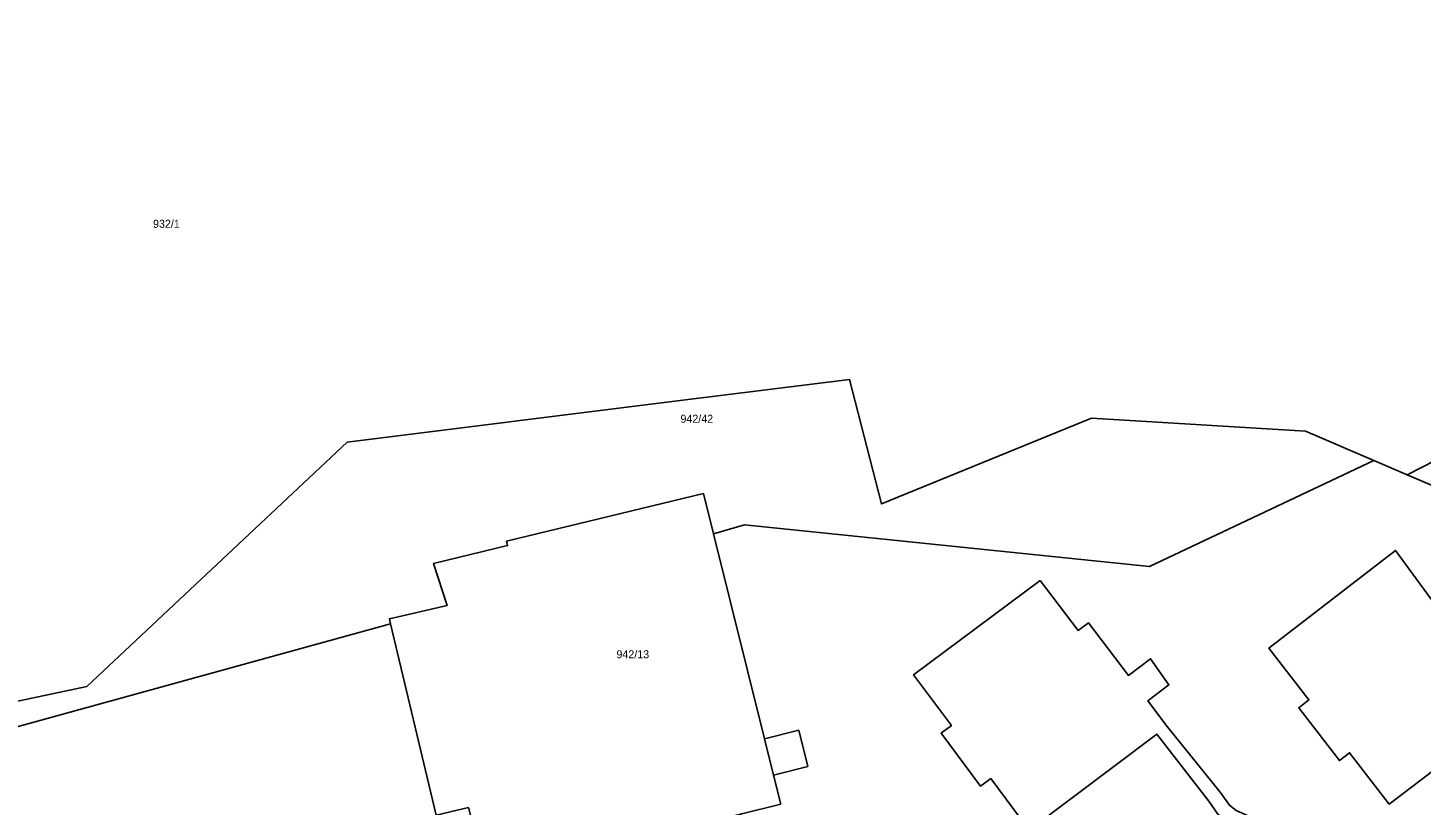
# Model space of a CAD drawing. Extents: x -793400 to -756198, y -1074141 to -1042963.
# Drawn here: x -783099 to -782968.4, y -1065113.7 to -1065040.9 of the extents above; entities that cross this region are included whole.
import ezdxf

# ---------------------------------------------------------------- set-up
doc = ezdxf.new("R2010")
doc.units = 0
for name, color, linetype in [('Parcela', 7, 'Continuous'), ('Popiskový text - Parcela', 7, 'Continuous'), ('Stavební objekt', 7, 'Continuous')]:
    doc.layers.add(name, color=color, linetype=linetype)

msp = doc.modelspace()

# ---------------------------------------------------------------- linework, layer by layer
at = {"layer": 'Parcela'}
for points in [[(-782898.51, -1065020.62), (-782948.33, -1065054.83), (-782960.53, -1065078.04), (-782969.74, -1065082.74), (-782972.88, -1065081.39), (-782979.27, -1065078.65), (-782999.34, -1065077.44), (-783019.03, -1065085.47), (-783022.01, -1065073.82), (-783037.89, -1065075.79), (-783069.1, -1065079.67), (-783093.52, -1065102.56), (-783130.63, -1065110.44), (-783148.72, -1065112.77), (-783166.26, -1065118.6), (-783200, -1065130.88), (-783236.01, -1065137.59), (-783242.83, -1065136.63), (-783249.82, -1065138.12)], [(-783130.63, -1065110.44), (-783093.52, -1065102.56), (-783069.1, -1065079.67), (-783037.89, -1065075.79), (-783022.01, -1065073.82), (-783019.03, -1065085.47), (-782999.34, -1065077.44), (-782979.27, -1065078.65), (-782972.88, -1065081.39), (-782993.91, -1065091.32), (-783031.87, -1065087.44), (-783034.78, -1065088.26), (-783035.72, -1065084.5), (-783054.18, -1065088.96), (-783054.08, -1065089.37), (-783061.01, -1065091.04), (-783059.74, -1065094.99), (-783065.15, -1065096.23), (-783065.04, -1065096.7), (-783145.19, -1065118.78)], [(-783145.19, -1065118.78), (-783065.04, -1065096.7), (-783060.76, -1065114.64), (-783057.74, -1065113.92), (-783056.04, -1065120.47), (-783037.14, -1065115.76), (-783036.87, -1065116.85), (-783031.97, -1065115.65), (-783032.24, -1065114.53), (-783028.46, -1065113.59), (-783029.14, -1065110.87), (-783025.94, -1065110.07), (-783026.78, -1065106.68), (-783029.99, -1065107.48), (-783034.78, -1065088.26), (-783031.87, -1065087.44), (-782993.91, -1065091.32), (-782972.88, -1065081.39), (-782969.74, -1065082.74), (-782964.46, -1065085)], [(-782967.25, -1065094.75), (-782970.84, -1065089.82), (-782982.71, -1065098.98), (-782978.96, -1065103.83), (-782979.91, -1065104.56), (-782976.09, -1065109.51), (-782975.14, -1065108.78), (-782971.43, -1065113.59), (-782959.66, -1065104.63)]]:
    msp.add_lwpolyline(points, dxfattribs=at)
for points in [[(-783034.78, -1065088.26), (-783029.99, -1065107.48), (-783026.78, -1065106.68), (-783025.94, -1065110.07), (-783029.14, -1065110.87), (-783028.46, -1065113.59), (-783032.24, -1065114.53), (-783031.97, -1065115.65), (-783036.87, -1065116.85), (-783037.14, -1065115.76), (-783056.04, -1065120.47), (-783057.74, -1065113.92), (-783060.76, -1065114.64), (-783065.04, -1065096.7), (-783065.15, -1065096.23), (-783059.74, -1065094.99), (-783061.01, -1065091.04), (-783054.08, -1065089.37), (-783054.18, -1065088.96), (-783035.72, -1065084.5)], [(-783004.14, -1065092.63), (-783016.02, -1065101.47), (-783012.47, -1065106.24), (-783013.43, -1065106.95), (-783009.74, -1065111.92), (-783008.78, -1065111.2), (-783005.18, -1065116.04), (-782993.21, -1065107.04), (-782988.33, -1065113.31), (-782987.48, -1065114.54), (-782986.34, -1065115.46), (-782979.93, -1065118.16), (-782981.55, -1065116.06), (-782985.78, -1065114.21), (-782986.41, -1065113.7), (-782987.26, -1065112.48), (-782992.25, -1065106.31), (-782994.06, -1065103.93), (-782992.08, -1065102.43), (-782993.8, -1065099.97), (-782995.87, -1065101.54), (-782999.62, -1065096.6), (-783000.58, -1065097.33)]]:
    msp.add_lwpolyline(points, close=True, dxfattribs=at)
at = {"layer": 'Stavební objekt'}
msp.add_lwpolyline([(-783028.46, -1065113.59), (-783032.24, -1065114.53), (-783037.14, -1065115.76), (-783056.04, -1065120.47), (-783057.74, -1065113.92), (-783060.76, -1065114.64), (-783065.04, -1065096.7), (-783065.15, -1065096.23), (-783059.74, -1065094.99), (-783061.01, -1065091.04), (-783054.08, -1065089.37), (-783054.18, -1065088.96), (-783035.72, -1065084.5), (-783034.78, -1065088.26), (-783029.99, -1065107.48), (-783029.14, -1065110.87)], close=True, dxfattribs=at)

# ---------------------------------------------------------------- texts
at = {"layer": 'Popiskový text - Parcela'}
for s, p in [('932/1', (-783087.31, -1065059.59)), ('942/42', (-783037.87, -1065077.86)), ('942/13', (-783043.87, -1065099.93))]:
    msp.add_text(s, height=0.75, dxfattribs=at).set_placement(p)

doc.saveas('drawing.dxf')
